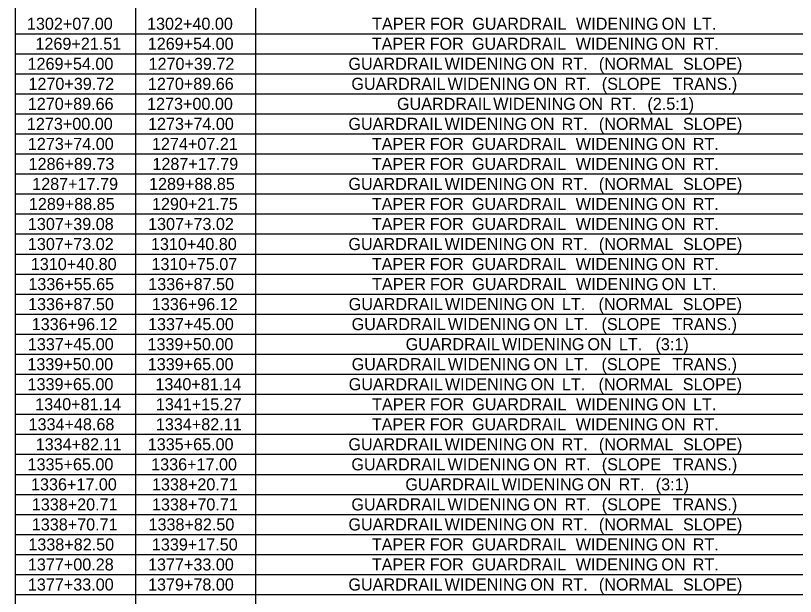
# Model space of a CAD drawing. Extents: x 1226590 to 1228573, y 151304 to 154224.
# Drawn here: x 1226590.3 to 1226844.3, y 151617.4 to 151806.5 of the extents above; entities that cross this region are included whole.
import ezdxf

# ---------------------------------------------------------------- set-up
doc = ezdxf.new("R2010")
doc.units = 0
doc.layers.add('R_Dimension', color=7, linetype='Continuous')

msp = doc.modelspace()

# ---------------------------------------------------------------- linework, layer by layer
at = {"layer": 'R_Dimension'}
for p, q in [((1226590.27, 151484.92), (1226590.27, 152182.03)), ((1226629.41, 151500.6), (1226629.41, 151957.19)), ((1226668.54, 151500.6), (1226668.54, 151957.19)), ((1226590.27, 151800.64), (1228150.73, 151800.64)), ((1226590.27, 151794.12), (1228150.73, 151794.12)), ((1226590.27, 151787.6), (1228150.73, 151787.6)), ((1226590.27, 151781.08), (1228150.73, 151781.08)), ((1226590.27, 151774.55), (1228150.73, 151774.55)), ((1226590.27, 151768.03), (1228150.73, 151768.03)), ((1226590.27, 151761.51), (1228150.73, 151761.51)), ((1226590.27, 151754.99), (1228150.73, 151754.99)), ((1226590.27, 151748.46), (1228150.73, 151748.46)), ((1226590.27, 151741.94), (1228150.73, 151741.94)), ((1226590.27, 151735.42), (1228150.73, 151735.42)), ((1226590.27, 151728.89), (1228150.73, 151728.89)), ((1226590.27, 151722.37), (1228150.73, 151722.37)), ((1226590.27, 151715.85), (1228150.73, 151715.85)), ((1226590.27, 151709.33), (1228150.73, 151709.33)), ((1226590.27, 151702.8), (1228150.73, 151702.8)), ((1226590.27, 151696.28), (1228150.73, 151696.28)), ((1226590.27, 151689.76), (1228150.73, 151689.76)), ((1226590.27, 151683.24), (1228150.73, 151683.24)), ((1226590.27, 151676.71), (1228150.73, 151676.71)), ((1226590.27, 151670.19), (1228150.73, 151670.19)), ((1226590.27, 151663.67), (1228150.73, 151663.67)), ((1226590.27, 151657.14), (1228150.73, 151657.14)), ((1226590.27, 151650.62), (1228150.73, 151650.62)), ((1226590.27, 151644.1), (1228150.73, 151644.1)), ((1226590.27, 151637.58), (1228150.73, 151637.58)), ((1226590.27, 151631.05), (1228150.73, 151631.05)), ((1226590.27, 151624.53), (1228150.73, 151624.53)), ((1226590.27, 151618.01), (1228150.73, 151618.01))]:
    msp.add_line(p, q, dxfattribs=at)

# ---------------------------------------------------------------- texts
for s, p in [('1302+07.00', (1226593.96, 151801.94)), ('1302+40.00', (1226633.09, 151801.94)), ('TAPER', (1226706.39, 151801.94)), (' FOR', (1226723.78, 151801.94)), (' GUARDRAIL', (1226737.53, 151801.94)), (' WIDENING', (1226771.34, 151801.94)), (' ON', (1226799.23, 151801.94)), (' LT.', (1226809.45, 151801.94)), ('1269+21.51', (1226596.73, 151795.42)), ('1269+54.00', (1226633.31, 151795.42)), ('TAPER', (1226706.3, 151795.42)), (' FOR', (1226723.68, 151795.42)), (' GUARDRAIL', (1226737.44, 151795.42)), (' WIDENING', (1226771.25, 151795.42)), (' ON', (1226799.14, 151795.42)), (' RT.', (1226809.36, 151795.42)), ('1269+54.00', (1226594.17, 151788.89)), ('1270+39.72', (1226633.57, 151788.89)), ('GUARDRAIL', (1226698.68, 151788.89)), (' WIDENING', (1226728.55, 151788.89)), (' ON', (1226756.44, 151788.89)), (' RT.', (1226766.66, 151788.89)), (' (NORMAL', (1226778.78, 151788.89)), (' SLOPE)', (1226806.2, 151788.89)), ('1270+39.72', (1226594.44, 151782.37)), ('1270+89.66', (1226633.37, 151782.37)), ('GUARDRAIL', (1226699.64, 151782.37)), (' WIDENING', (1226729.51, 151782.37)), (' ON', (1226757.4, 151782.37)), (' RT.', (1226767.62, 151782.37)), (' (SLOPE', (1226779.74, 151782.37)), (' TRANS.)', (1226802.82, 151782.37)), ('1270+89.66', (1226594.24, 151775.85)), ('1273+00.00', (1226633.09, 151775.85)), ('GUARDRAIL', (1226714.5, 151775.85)), (' WIDENING', (1226744.37, 151775.85)), (' ON', (1226772.26, 151775.85)), (' (2.5:1)', (1226794.6, 151775.85)), (' RT.', (1226782.48, 151775.85)), ('1273+00.00', (1226593.96, 151769.32)), ('1273+74.00', (1226633.4, 151769.32)), ('GUARDRAIL', (1226698.68, 151769.32)), (' WIDENING', (1226728.55, 151769.32)), (' ON', (1226756.44, 151769.32)), (' RT.', (1226766.66, 151769.32)), (' (NORMAL', (1226778.78, 151769.32)), (' SLOPE)', (1226806.2, 151769.32)), ('1273+74.00', (1226594.27, 151762.8)), ('1274+07.21', (1226634.69, 151762.8)), ('TAPER', (1226706.3, 151762.8)), (' FOR', (1226723.68, 151762.8)), (' GUARDRAIL', (1226737.44, 151762.8)), (' WIDENING', (1226771.25, 151762.8)), (' ON', (1226799.14, 151762.8)), (' RT.', (1226809.36, 151762.8)), ('1286+89.73', (1226594.5, 151756.28)), ('1287+17.79', (1226634.83, 151756.28)), ('TAPER', (1226706.3, 151756.28)), (' FOR', (1226723.68, 151756.28)), (' GUARDRAIL', (1226737.44, 151756.28)), (' WIDENING', (1226771.25, 151756.28)), (' ON', (1226799.14, 151756.28)), (' RT.', (1226809.36, 151756.28)), ('1287+17.79', (1226595.69, 151749.76)), ('1289+88.85', (1226633.73, 151749.76)), ('GUARDRAIL', (1226698.68, 151749.76)), (' WIDENING', (1226728.55, 151749.76)), (' ON', (1226756.44, 151749.76)), (' RT.', (1226766.66, 151749.76)), (' (NORMAL', (1226778.78, 151749.76)), (' SLOPE)', (1226806.2, 151749.76)), ('1289+88.85', (1226594.59, 151743.23)), ('1290+21.75', (1226634.69, 151743.23)), ('TAPER', (1226706.3, 151743.23)), (' FOR', (1226723.68, 151743.23)), (' GUARDRAIL', (1226737.44, 151743.23)), (' WIDENING', (1226771.25, 151743.23)), (' ON', (1226799.14, 151743.23)), (' RT.', (1226809.36, 151743.23)), ('1307+39.08', (1226594.28, 151736.71)), ('1307+73.02', (1226633.42, 151736.71)), ('TAPER', (1226706.3, 151736.71)), (' FOR', (1226723.68, 151736.71)), (' GUARDRAIL', (1226737.44, 151736.71)), (' WIDENING', (1226771.25, 151736.71)), (' ON', (1226799.14, 151736.71)), (' RT.', (1226809.36, 151736.71)), ('1307+73.02', (1226594.28, 151730.19)), ('1310+40.80', (1226634.36, 151730.19)), ('GUARDRAIL', (1226698.68, 151730.19)), (' WIDENING', (1226728.55, 151730.19)), (' ON', (1226756.44, 151730.19)), (' RT.', (1226766.66, 151730.19)), (' (NORMAL', (1226778.78, 151730.19)), (' SLOPE)', (1226806.2, 151730.19)), ('1310+40.80', (1226595.23, 151723.67)), ('1310+75.07', (1226634.53, 151723.67)), ('TAPER', (1226706.3, 151723.67)), (' FOR', (1226723.68, 151723.67)), (' GUARDRAIL', (1226737.44, 151723.67)), (' WIDENING', (1226771.25, 151723.67)), (' ON', (1226799.14, 151723.67)), (' RT.', (1226809.36, 151723.67)), ('1336+55.65', (1226594.41, 151717.14)), ('1336+87.50', (1226633.47, 151717.14)), ('TAPER', (1226706.39, 151717.14)), (' FOR', (1226723.78, 151717.14)), (' GUARDRAIL', (1226737.53, 151717.14)), (' WIDENING', (1226771.34, 151717.14)), (' ON', (1226799.23, 151717.14)), (' LT.', (1226809.45, 151717.14)), ('1336+87.50', (1226594.33, 151710.62)), ('1336+96.12', (1226634.66, 151710.62)), ('GUARDRAIL', (1226698.77, 151710.62)), (' WIDENING', (1226728.64, 151710.62)), (' ON', (1226756.53, 151710.62)), (' LT.', (1226766.76, 151710.62)), (' (NORMAL', (1226778.68, 151710.62)), (' SLOPE)', (1226806.11, 151710.62)), ('1336+96.12', (1226595.52, 151704.1)), ('1337+45.00', (1226633.4, 151704.1)), ('GUARDRAIL', (1226699.73, 151704.1)), (' WIDENING', (1226729.6, 151704.1)), (' ON', (1226757.49, 151704.1)), (' LT.', (1226767.72, 151704.1)), (' (SLOPE', (1226779.65, 151704.1)), (' TRANS.)', (1226802.73, 151704.1)), ('1337+45.00', (1226594.27, 151697.57)), ('1339+50.00', (1226633.25, 151697.57)), ('GUARDRAIL', (1226717.32, 151697.57)), (' WIDENING', (1226747.19, 151697.57)), (' ON', (1226775.07, 151697.57)), (' LT.', (1226785.3, 151697.57)), (' (3:1)', (1226797.23, 151697.57)), ('1339+50.00', (1226594.11, 151691.05)), ('1339+65.00', (1226633.31, 151691.05)), ('GUARDRAIL', (1226699.73, 151691.05)), (' WIDENING', (1226729.6, 151691.05)), (' ON', (1226757.49, 151691.05)), (' LT.', (1226767.72, 151691.05)), (' (SLOPE', (1226779.65, 151691.05)), (' TRANS.)', (1226802.73, 151691.05)), ('1339+65.00', (1226594.17, 151684.53)), ('1340+81.14', (1226635.81, 151684.53)), ('GUARDRAIL', (1226698.77, 151684.53)), (' WIDENING', (1226728.64, 151684.53)), (' ON', (1226756.53, 151684.53)), (' LT.', (1226766.76, 151684.53)), (' (NORMAL', (1226778.68, 151684.53)), (' SLOPE)', (1226806.11, 151684.53)), ('1340+81.14', (1226596.67, 151678.01)), ('1341+15.27', (1226635.96, 151678.01)), ('TAPER', (1226706.39, 151678.01)), (' FOR', (1226723.78, 151678.01)), (' GUARDRAIL', (1226737.53, 151678.01)), (' WIDENING', (1226771.34, 151678.01)), (' ON', (1226799.23, 151678.01)), (' LT.', (1226809.45, 151678.01)), ('1334+48.68', (1226594.5, 151671.48)), ('1334+82.11', (1226635.96, 151671.48)), ('TAPER', (1226706.3, 151671.48)), (' FOR', (1226723.68, 151671.48)), (' GUARDRAIL', (1226737.44, 151671.48)), (' WIDENING', (1226771.25, 151671.48)), (' ON', (1226799.14, 151671.48)), (' RT.', (1226809.36, 151671.48)), ('1334+82.11', (1226596.82, 151664.96)), ('1335+65.00', (1226633.31, 151664.96)), ('GUARDRAIL', (1226698.68, 151664.96)), (' WIDENING', (1226728.55, 151664.96)), (' ON', (1226756.44, 151664.96)), (' RT.', (1226766.66, 151664.96)), (' (NORMAL', (1226778.78, 151664.96)), (' SLOPE)', (1226806.2, 151664.96)), ('1335+65.00', (1226594.17, 151658.44)), ('1336+17.00', (1226634.43, 151658.44)), ('GUARDRAIL', (1226699.64, 151658.44)), (' WIDENING', (1226729.51, 151658.44)), (' ON', (1226757.4, 151658.44)), (' RT.', (1226767.62, 151658.44)), (' (SLOPE', (1226779.74, 151658.44)), (' TRANS.)', (1226802.82, 151658.44)), ('1336+17.00', (1226595.29, 151651.92)), ('1338+20.71', (1226634.69, 151651.92)), ('GUARDRAIL', (1226717.22, 151651.92)), (' WIDENING', (1226747.09, 151651.92)), (' ON', (1226774.98, 151651.92)), (' RT.', (1226785.21, 151651.92)), (' (3:1)', (1226797.32, 151651.92)), ('1338+20.71', (1226595.55, 151645.39)), ('1338+70.71', (1226634.69, 151645.39)), ('GUARDRAIL', (1226699.64, 151645.39)), (' WIDENING', (1226729.51, 151645.39)), (' ON', (1226757.4, 151645.39)), (' RT.', (1226767.62, 151645.39)), (' (SLOPE', (1226779.74, 151645.39)), (' TRANS.)', (1226802.82, 151645.39)), ('1338+70.71', (1226595.55, 151638.87)), ('1338+82.50', (1226633.56, 151638.87)), ('GUARDRAIL', (1226698.68, 151638.87)), (' WIDENING', (1226728.55, 151638.87)), (' ON', (1226756.44, 151638.87)), (' RT.', (1226766.66, 151638.87)), (' (NORMAL', (1226778.78, 151638.87)), (' SLOPE)', (1226806.2, 151638.87)), ('1338+82.50', (1226594.42, 151632.35)), ('1339+17.50', (1226634.67, 151632.35)), ('TAPER', (1226706.3, 151632.35)), (' FOR', (1226723.68, 151632.35)), (' GUARDRAIL', (1226737.44, 151632.35)), (' WIDENING', (1226771.25, 151632.35)), (' ON', (1226799.14, 151632.35)), (' RT.', (1226809.36, 151632.35)), ('1377+00.28', (1226594.28, 151625.83)), ('1377+33.00', (1226633.4, 151625.83)), ('TAPER', (1226706.3, 151625.83)), (' FOR', (1226723.68, 151625.83)), (' GUARDRAIL', (1226737.44, 151625.83)), (' WIDENING', (1226771.25, 151625.83)), (' ON', (1226799.14, 151625.83)), (' RT.', (1226809.36, 151625.83)), ('1377+33.00', (1226594.27, 151619.3)), ('1379+78.00', (1226633.4, 151619.3)), ('GUARDRAIL', (1226698.68, 151619.3)), (' WIDENING', (1226728.55, 151619.3)), (' ON', (1226756.44, 151619.3)), (' RT.', (1226766.66, 151619.3)), (' (NORMAL', (1226778.78, 151619.3)), (' SLOPE)', (1226806.2, 151619.3))]:
    msp.add_text(s, height=3.935, dxfattribs=at).set_placement(p)

doc.saveas('drawing.dxf')
